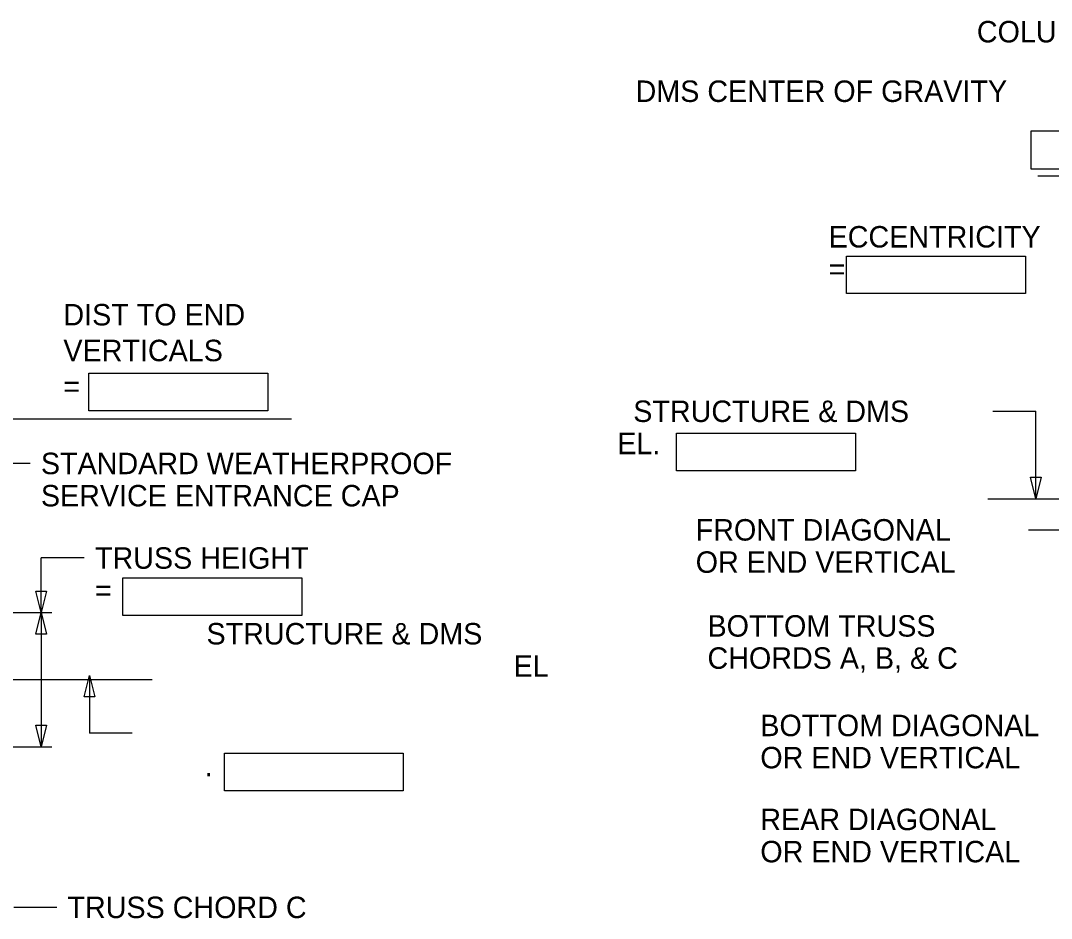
# Model space of a CAD drawing. Extents: x 3831399 to 3833095, y 499014 to 500202.
# Drawn here: x 3832754.1 to 3832893.8, y 499867.2 to 499988.9 of the extents above; entities that cross this region are included whole.
import ezdxf

# ---------------------------------------------------------------- set-up
doc = ezdxf.new("R2010")
doc.units = 0
for name, color, linetype in [('CenterLine', 7, 'Continuous'), ('Default', 7, 'Continuous'), ('DIM TXT', 7, 'Continuous')]:
    doc.layers.add(name, color=color, linetype=linetype)

msp = doc.modelspace()

# ---------------------------------------------------------------- linework, layer by layer
at = {"layer": 'CenterLine'}
for p, q in [((3832885.2, 499924.07), (3832976.25, 499924.07)), ((3832308.87, 499899.55), (3832771.9, 499899.55))]:
    msp.add_line(p, q, dxfattribs=at)
at = {"layer": 'Default'}
for p, q in [((3832866.05, 499956.96), (3832890.3, 499956.96)), ((3832866.05, 499951.87), (3832866.05, 499956.96)), ((3832890.3, 499956.96), (3832890.3, 499951.87)), ((3832890.3, 499951.87), (3832866.05, 499951.87)), ((3832763.32, 499941.09), (3832787.57, 499941.09)), ((3832763.32, 499936), (3832763.32, 499941.09)), ((3832787.57, 499941.09), (3832787.57, 499936)), ((3832787.57, 499936), (3832763.32, 499936)), ((3832843, 499932.96), (3832867.25, 499932.96)), ((3832843, 499927.86), (3832843, 499932.96)), ((3832867.25, 499932.96), (3832867.25, 499927.86)), ((3832867.25, 499927.86), (3832843, 499927.86)), ((3832767.95, 499913.33), (3832792.2, 499913.33)), ((3832767.95, 499908.24), (3832767.95, 499913.33)), ((3832792.2, 499913.33), (3832792.2, 499908.24)), ((3832792.2, 499908.24), (3832767.95, 499908.24)), ((3832781.7, 499889.58), (3832805.95, 499889.58)), ((3832781.7, 499884.49), (3832781.7, 499889.58)), ((3832805.95, 499889.58), (3832805.95, 499884.49)), ((3832805.95, 499884.49), (3832781.7, 499884.49))]:
    msp.add_line(p, q, dxfattribs=at)
at = {"layer": 'DIM TXT'}
for p, q in [((3832915.29, 499973.87), (3832891.04, 499973.87)), ((3832891.04, 499973.87), (3832891.04, 499968.78)), ((3832891.04, 499968.78), (3832915.29, 499968.78)), ((3832916.07, 499967.79), (3832891.98, 499967.79)), ((3832885.9, 499935.93), (3832891.72, 499935.93)), ((3832891.71, 499924.07), (3832891.72, 499935.93)), ((3832790.78, 499934.87), (3832746.49, 499934.87)), ((3832755.37, 499928.85), (3832749.55, 499928.85)), ((3832890.71, 499919.85), (3832896.53, 499919.85)), ((3832756.85, 499908.64), (3832756.87, 499916.04)), ((3832762.69, 499916.04), (3832756.87, 499916.04)), ((3832747.95, 499908.64), (3832758.3, 499908.64)), ((3832756.85, 499908.64), (3832756.85, 499890.46)), ((3832763.41, 499900.12), (3832763.4, 499892.3)), ((3832769.21, 499892.3), (3832763.4, 499892.3)), ((3832747.95, 499890.46), (3832758.3, 499890.46)), ((3832758.97, 499868.69), (3832753.15, 499868.69)), ((3832758.97, 499868.69), (3832753.15, 499868.69))]:
    msp.add_line(p, q, dxfattribs=at)
for points in [[(3832892.44, 499926.98), (3832891.71, 499924.07), (3832890.98, 499926.98)], [(3832757.59, 499911.55), (3832756.85, 499908.64), (3832756.13, 499911.56)], [(3832756.12, 499905.73), (3832756.85, 499908.64), (3832757.58, 499905.73)], [(3832762.68, 499897.21), (3832763.41, 499900.12), (3832764.13, 499897.21)], [(3832757.58, 499893.37), (3832756.85, 499890.46), (3832756.12, 499893.37)]]:
    msp.add_lwpolyline(points, close=True, dxfattribs=at)

# ---------------------------------------------------------------- texts
for s, height, p in [('  COLUMN', 2.91, (3832881.56, 499985.92)), ('DMS CENTER OF GRAVITY', 2.9099, (3832837.45, 499977.85)), ('ECCENTRICITY', 2.9099, (3832863.62, 499958.12)), ('=', 2.91, (3832863.62, 499953.76)), ('DIST TO END', 2.9099, (3832759.87, 499947.56)), ('VERTICALS', 2.91, (3832759.87, 499942.71)), ('=', 2.91, (3832759.87, 499937.86)), ('  STRUCTURE & DMS', 2.9099, (3832834.97, 499934.47)), ('EL.', 2.91, (3832834.97, 499930.11)), ('STANDARD WEATHERPROOF', 2.9099, (3832756.82, 499927.4)), ('SERVICE ENTRANCE CAP', 2.9099, (3832756.82, 499923.03)), ('FRONT DIAGONAL ', 2.9099, (3832845.6, 499918.4)), ('TRUSS HEIGHT', 2.9099, (3832764.15, 499914.58)), ('OR END VERTICAL', 2.9099, (3832845.6, 499914.03)), ('=', 2.91, (3832764.15, 499910.22)), ('BOTTOM TRUSS', 2.9099, (3832847.2, 499905.38)), ('  STRUCTURE & DMS', 2.9099, (3832777.11, 499904.32)), ('CHORDS A, B, & C', 2.9099, (3832847.2, 499901.02)), ('EL              ', 2.9099, (3832820.9, 499899.95)), ('BOTTOM DIAGONAL', 2.9099, (3832854.36, 499891.89)), ('OR END VERTICAL', 2.9099, (3832854.36, 499887.53)), ('.', 2.91, (3832779.01, 499886.43)), ('REAR DIAGONAL', 2.9099, (3832854.36, 499879.15)), ('OR END VERTICAL', 2.9099, (3832854.36, 499874.79)), ('TRUSS CHORD C', 2.9099, (3832760.42, 499867.23))]:
    msp.add_text(s, height=height, dxfattribs=at).set_placement(p)

doc.saveas('drawing.dxf')
